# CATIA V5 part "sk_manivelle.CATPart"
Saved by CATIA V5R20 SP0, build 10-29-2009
Part number: sk_manivelle
Publications: "Point.1", "Point.3", "Droite.1", "Droite.2", "Droite.3", "Plan.1", "Plan.2"
Bounding box of the stored display mesh (mm): x -20 to 20, y 0 to 27.953, z 10 to 20.891
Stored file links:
  D:\Dropbox\IAO_2011\MMS_GR2\IAO_2011_1495_fpittorino\fpittorino_IAO\IAO_2011_1495_fpittorino\sk_manivelle.CATPart
  D:\Dropbox\IAO_2011\MMS_GR2\IAO_2011_1495_fpittorino\fpittorino_IAO\IAO_2011_1495_fpittorino\Product3.CATProduct
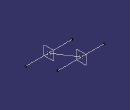
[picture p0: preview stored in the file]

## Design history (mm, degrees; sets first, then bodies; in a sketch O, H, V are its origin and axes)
Set1
  Point1: linked copy from another document
  Point2: linked copy from another document
Body1 (main body)
  Point3: (0, 0, 0), relative to Point1
  Point4: (0, 0, 0), relative to Point2
  Line1: type PtPt, FirstPoint Point3, SecondPoint Point4
  Line2: type Normal, RefPoint Point3, RefSkin yz-plane, Start -20, End 20
  Line3: type Normal, RefPoint Point4, RefSkin yz-plane, Start -20, End 20
  Plane1: type Normal, Curve Line3, RefPoint Point4
  Plane2: type Normal, Curve Line2, RefPoint Point3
